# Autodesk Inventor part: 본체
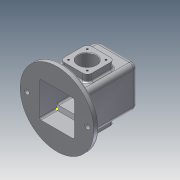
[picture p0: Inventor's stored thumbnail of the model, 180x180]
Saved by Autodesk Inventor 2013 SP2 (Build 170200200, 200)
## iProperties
Created: 2021-08
Part Number: 본체
Material: 알루미늄 6061
Document SubType Name: Modeling
Designer: kumcom17
Density: 2.71 g/cm^3
Mass: 882.571 g
Surface Area: 934.848 cm^2
Volume: 325.672 cm^3
Author: kumcom17
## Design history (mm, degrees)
sketch "스케치1"
  geometry: C1 r 67 at (0, 0); 1 further point
  constraints: 1 centre point, 1 coincident
  dimensions: "d0" = 134 diameter of C1
extrude "돌출1" new body sketch "스케치1" distance "d2" = 10; taper "d3" = 0 deg
sketch "스케치2"
  geometry: L1 (-37, 37)-(37, 37); L2 (37, 37)-(37, -37); L3 (37, -37)-(-37, -37); L4 (-37, -37)-(-37, 37); L5 (-37, 37)-(37, -37); L6 (37, 37)-(-37, -37); C1 r 67 at (0, 0) reference
  constraints: 12 end point, 2 midpoint, 2 parallel, 1 horizontal, 1 perpendicular
  dimensions: "d4" = 74 distance of L1.start L1.end; "d6" = 74 distance of L1.end L2.end
extrude "돌출2" join sketch "스케치2" distance "d7" = 100; taper "d8" = 0 deg
fillet "모깎기1" dims "d9" = 8
sketch "스케치3"
  geometry: C1 r 20 at (0, 0); 1 further point
  constraints: 1 centre point, 1 coincident
  dimensions: "d10" = 40 diameter of C1
extrude "돌출3" join sketch "스케치3" distance "d13" = 10; taper "d14" = -6 deg
sketch "스케치4"
  geometry: L1 (66, 0)-(66, 100) reference; L2 (29, 0)-(29, 100); L3 (-38, -10)-(96, -10) reference; L4 (-38, 45)-(96, 45); L5 (4, 70)-(54, 70); L6 (54, 70)-(54, 20); L7 (54, 20)-(4, 20); L8 (4, 20)-(4, 70); L9 (4, 70)-(54, 20); L10 (54, 70)-(4, 20); 2 further points
  constraints: 16 end point, 4 parallel, 3 midpoint, 1 horizontal, 1 perpendicular
  dimensions: "d15" = 37 distance between parallel lines of L1 L2; "d16" = 55 distance between parallel lines of L3 L4; "d17" = 50 distance of L5.start L5.end; "d18" = 50 distance of L5.end L6.end
extrude "돌출4" join sketch "스케치4" distance "d19" = 13; taper "d20" = 0 deg
fillet "모깎기2" dims "d21" = 8
hole "구멍1" diameter "d24" = 28; stored, may be unused: countersink angle "d28" = 90 deg, drill point angle "d30" = 0 deg; dims "d22" = 10, "d23" = 10, "d25" = 6, "d26" = 4, "d27" = 2, "d29" = 4
sketch "스케치5"
  geometry: L1 (42, 42)-(42, 8) reference; C1 r 16 at (17, 25); 1 further point
  constraints: 1 centre point
  dimensions: "d31" = 32 diameter of C1
extrude "돌출5" cut sketch "스케치5" stored distance "d33" = 13; taper "d34" = 0 deg
sketch "스케치7"
  geometry: 1 further point
sketch "스케치8"
  geometry: L1 (0, 0)-(0, -32); L2 (0, -32)-(30, -32); L3 (30, -32)-(32.548, -25); L4 (57.548, -25)-(57.548, 0); L5 (0, 0)-(0, 32); L6 (0, 32)-(30, 32); L7 (30, 32)-(32.548, 25); L8 (110, 37)-(110, 29) reference; L9 (80, 32)-(105, 32); L10 (110, -29)-(110, -37) reference; L11 (99.904, 0)-(30, 0); L12 (110, -37)-(10, -37) reference; L13 (105, -32)-(80, -32); L14 (57.548, 25)-(57.548, -25); L15 (32.548, 25)-(77.452, 25); L16 (80, 32)-(77.452, 25); L17 (32.548, -25)-(77.452, -25); L18 (80, -32)-(77.452, -25); L19 (105, 32)-(105, -32)
  constraints: 32 end point, 4 perpendicular, 3 parallel, 1 collinear, 1 symmetric about line, 1 vertical
  dimensions: "d43" = 32 distance of L1.start L1.end; "d44" = 30 distance of L1.end L2.end; "d46" = 110 deg angle of L2 L3; "d47" = 25 distance of L3.end L4.start; "d48" = 32 distance of L1.start L5.end; "d49" = 30 distance of L5.end L6.end; "d51" = 110 deg angle of L6 L7; "d94" = 50 distance of L6.end L9.start; "d95" = 50 distance of L2.end L13.end; "d96" = 110 deg angle of L9 L16
extrude "돌출6" cut sketch "스케치8" stored distance "d59" = 64; taper "d60" = 0 deg
hole "구멍2" diameter "d63" = 21; stored, may be unused: countersink angle "d67" = 90 deg, drill point angle "d69" = 0 deg; dims "d61" = 10, "d62" = 10, "d64" = 6, "d65" = 4, "d66" = 2, "d68" = 4
sketch "스케치9"
  geometry: A1 r 8 centre (0, 8) between (-8, 8) and (0, 0) reference; A2 r 8 centre (34, 8) between (34, 0) and (42, 8) reference; A3 r 8 centre (34, 42) between (42, 42) and (34, 50) reference; A4 r 8 centre (0, 42) between (0, 50) and (-8, 42) reference; 5 further points
  constraints: 4 coincident
hole "구멍3" sketch "스케치9" at (0, 42), (34, 42), (34, 8), (0, 8) diameter "d70" = 3.242; stored, may be unused: countersink angle "d74" = 90 deg, drill point angle "d76" = 118 deg; dims "d71" = 8, "d72" = 4, "d73" = 2, "d75" = 10
sketch "스케치10"
  geometry: A1 r 8 centre (12, 28) between (4, 28) and (12, 20) reference; A2 r 8 centre (46, 28) between (46, 20) and (54, 28) reference; A3 r 8 centre (46, 62) between (54, 62) and (46, 70) reference; A4 r 8 centre (12, 62) between (12, 70) and (4, 62) reference; 5 further points
  constraints: 4 coincident
hole "구멍4" sketch "스케치10" at (46, 62), (12, 62), (12, 28), (46, 28) diameter "d77" = 3.242; stored, may be unused: countersink angle "d81" = 90 deg, drill point angle "d83" = 118 deg; dims "d78" = 8, "d79" = 4, "d80" = 2, "d82" = 10
fillet "모깎기3" dims "d84" = 3
fillet "모깎기4" dims "d85" = 8
chamfer "모따기1" distance "d86" = 1; stored, may be unused: second distance "d87" = 2, angle "d88" = 45 deg
sketch "스케치11"
  geometry: 1 further point
fillet "모깎기5" dims "d89" = 3
sketch "스케치12"
  geometry: L1 (-8, 89)-(-8, 0) reference; L2 (10.051, 107)-(47.949, 107) reference; 2 further points
  constraints: 1 other
  dimensions: "d90" = 37 distance from line of L1 point (29, 79); "d91" = 28 distance from line of point (29, 79) L2
feature "엠보싱1" sketch "스케치12" dims "d92" = 0.5, "d93" = 0
fillet "모깎기6" dims "d98" = 3
fillet "모깎기7" dims "d99" = 3
sketch "스케치13"
  geometry: C1 r 64 at (0, 0) reference; A1 r 55 centre (0, 0) between (0, 55) and (0, -55); 3 further points
  constraints: 4 point on circle, 2 coincident, 1 centre point
  dimensions: "d100" = 110 diameter of A1
hole "구멍5" sketch "스케치13" at (-55, 0), (55, 0) diameter "d102" = 9; stored, may be unused: countersink angle "d106" = 90 deg, drill point angle "d108" = 0 deg; dims "d103" = 8, "d104" = 4, "d105" = 2, "d107" = 10
fillet "모깎기8" dims "d109" = 3
node "솔리드1"
mirror "대칭1"
other parameters: "d39" = 7
